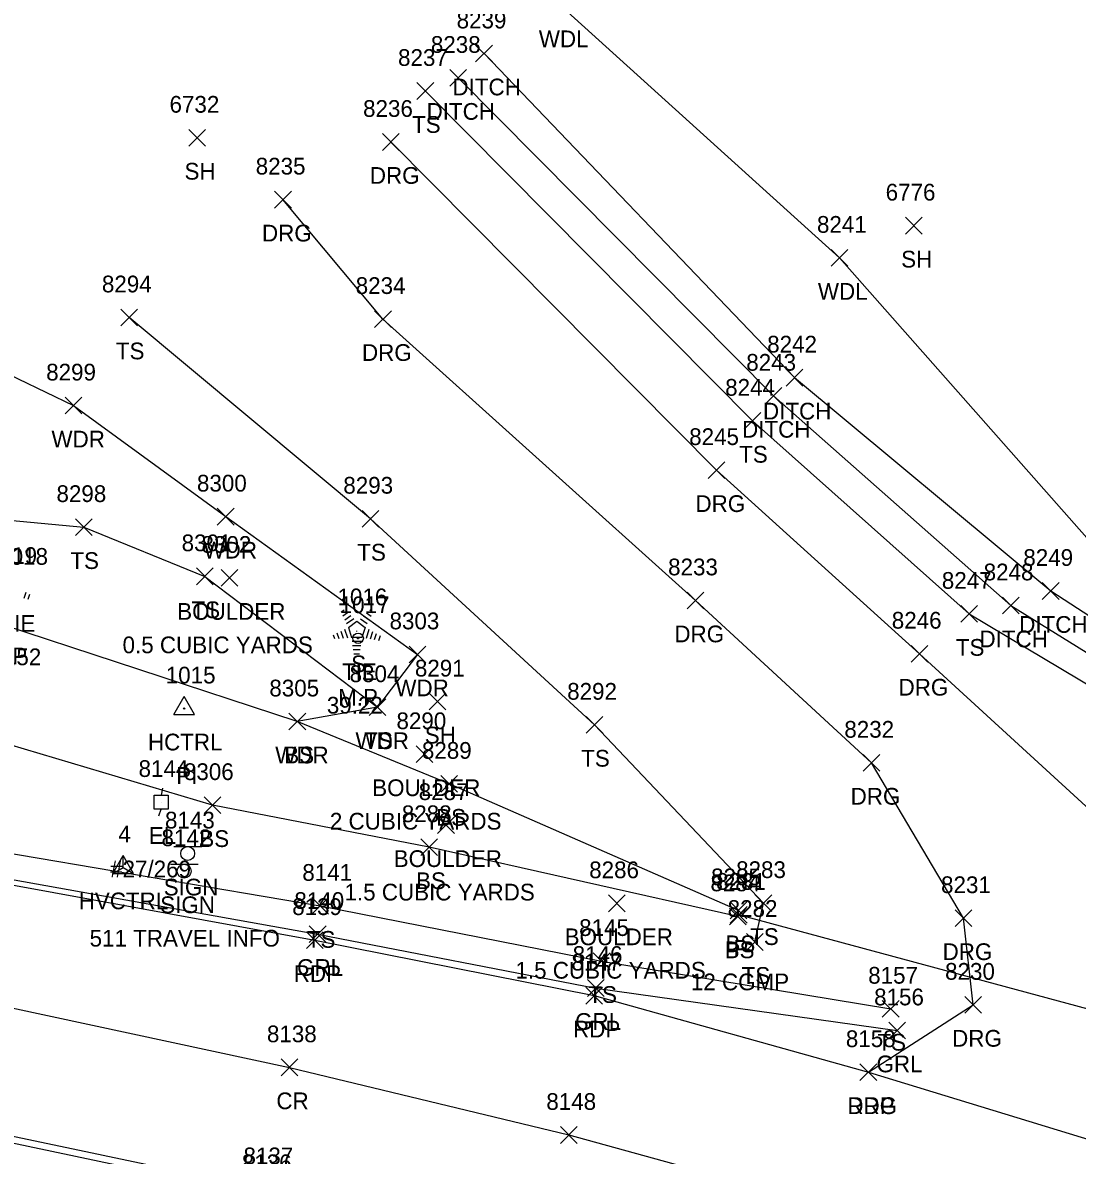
# Model space of a CAD drawing. Extents: x 1588028 to 1589597, y 137576 to 138176.
# Drawn here: x 1588986.3 to 1589112.3, y 137833.8 to 137969.2 of the extents above; entities that cross this region are included whole.
import ezdxf

# ---------------------------------------------------------------- set-up
doc = ezdxf.new("R2010")
doc.units = 0
for name, color, linetype in [('C_A', 7, 'Continuous'), ('C_C', 7, 'Continuous'), ('C_I', 7, 'Continuous'), ('CBP', 7, 'Continuous'), ('CPH', 7, 'Continuous'), ('CPSM', 7, 'Continuous'), ('D_A', 7, 'Continuous'), ('D_C', 7, 'Continuous'), ('D_I', 7, 'Continuous'), ('D_TIC', 7, 'Continuous'), ('DCP', 7, 'Continuous'), ('DD', 7, 'Continuous'), ('L_A', 7, 'Continuous'), ('L_C', 7, 'Continuous'), ('L_I', 7, 'Continuous'), ('L_TIC', 7, 'Continuous'), ('LAWA', 7, 'Continuous'), ('LELB', 7, 'Continuous'), ('LTC', 7, 'Continuous'), ('P_A', 7, 'Continuous'), ('P_I', 7, 'Continuous'), ('P_TIC', 7, 'Continuous'), ('PET', 7, 'Continuous'), ('PRC', 7, 'Continuous'), ('R_A', 7, 'Continuous'), ('R_I', 7, 'Continuous'), ('R_TIC', 7, 'Continuous'), ('RDG', 7, 'Continuous'), ('RGR', 7, 'Continuous'), ('S_A', 7, 'Continuous'), ('S_C', 7, 'Continuous'), ('S_I', 7, 'Continuous'), ('SSGN', 7, 'Continuous'), ('U_A', 7, 'Continuous'), ('U_C', 7, 'Continuous'), ('U_I', 7, 'Continuous'), ('UEPT', 7, 'Continuous')]:
    doc.layers.add(name, color=color, linetype=linetype)

msp = doc.modelspace()

# ---------------------------------------------------------------- linework, layer by layer
at = {"layer": 'CBP'}
for radius in [0.625, 0.0833]:
    msp.add_circle((1589026.39, 137895.62), radius, dxfattribs=at)
at = {"layer": 'CPH'}
for p, q in [((1589004.35, 137886.5), (1589005.6, 137888.66)), ((1589006.85, 137886.5), (1589005.6, 137888.66)), ((1589004.35, 137886.5), (1589006.85, 137886.5)), ((1589005.6, 137887.22), (1589005.6, 137887.22))]:
    msp.add_line(p, q, dxfattribs=at)
msp.add_circle((1589005.6, 137887.22), 0.0833, dxfattribs=at)
at = {"layer": 'CPSM'}
for p, q in [((1588997.06, 137867.52), (1588998.31, 137869.68)), ((1588999.56, 137867.52), (1588998.31, 137869.68)), ((1588998.31, 137868.24), (1588998.31, 137869.68)), ((1588997.06, 137867.52), (1588998.31, 137868.24)), ((1588997.06, 137867.52), (1588999.56, 137867.52)), ((1588998.31, 137868.24), (1588998.31, 137868.24)), ((1588998.31, 137868.24), (1588999.56, 137867.52))]:
    msp.add_line(p, q, dxfattribs=at)
at = {"layer": 'D_TIC'}
for points in [[(1589040.43, 137964.49), (1589042.43, 137966.49)], [(1589042.43, 137964.49), (1589040.43, 137966.49)], [(1589037.34, 137961.57), (1589039.34, 137963.57)], [(1589039.34, 137961.57), (1589037.34, 137963.57)], [(1589077.53, 137925.76), (1589079.53, 137927.76)], [(1589079.53, 137925.76), (1589077.53, 137927.76)], [(1589075.03, 137923.59), (1589077.03, 137925.59)], [(1589077.03, 137923.59), (1589075.03, 137925.59)], [(1589108.15, 137900.27), (1589110.15, 137902.27)], [(1589110.15, 137900.27), (1589108.15, 137902.27)], [(1589103.4, 137898.54), (1589105.4, 137900.54)], [(1589105.4, 137898.54), (1589103.4, 137900.54)], [(1589070.86, 137861.56), (1589072.86, 137863.56)], [(1589072.86, 137861.56), (1589070.86, 137863.56)]]:
    msp.add_lwpolyline(points, dxfattribs=at)
at = {"layer": 'DCP'}
msp.add_lwpolyline([(1589168.99, 137836.35), (1589071.86, 137862.56)], dxfattribs=at)
at = {"layer": 'DD'}
for points in [[(1589041.43, 137965.49), (1589078.53, 137926.76), (1589109.15, 137901.27), (1589128.72, 137888.57), (1589151.77, 137873.1)], [(1589038.34, 137962.57), (1589076.03, 137924.59), (1589104.4, 137899.54), (1589125.75, 137886.32), (1589152.64, 137869.01)]]:
    msp.add_lwpolyline(points, dxfattribs=at)
at = {"layer": 'L_TIC'}
for points in [[(1589033.42, 137960.01), (1589035.42, 137962.01)], [(1589035.42, 137960.01), (1589033.42, 137962.01)], [(1589006.15, 137954.42), (1589008.15, 137956.42)], [(1589008.15, 137954.42), (1589006.15, 137956.42)], [(1589091.8, 137943.92), (1589093.8, 137945.92)], [(1589093.8, 137943.92), (1589091.8, 137945.92)], [(1589082.91, 137940.07), (1589084.91, 137942.07)], [(1589084.91, 137940.07), (1589082.91, 137942.07)], [(1588998.03, 137932.95), (1589000.03, 137934.95)], [(1589000.03, 137932.95), (1588998.03, 137934.95)], [(1588991.38, 137922.42), (1588993.38, 137924.42)], [(1588993.38, 137922.42), (1588991.38, 137924.42)], [(1589072.51, 137920.6), (1589074.51, 137922.6)], [(1589074.51, 137920.6), (1589072.51, 137922.6)], [(1589009.56, 137909.15), (1589011.56, 137911.15)], [(1589011.56, 137909.15), (1589009.56, 137911.15)], [(1589026.88, 137908.9), (1589028.88, 137910.9)], [(1589028.88, 137908.9), (1589026.88, 137910.9)], [(1588992.6, 137907.9), (1588994.6, 137909.9)], [(1588994.6, 137907.9), (1588992.6, 137909.9)], [(1589007.07, 137902.02), (1589009.07, 137904.02)], [(1589009.07, 137902.02), (1589007.07, 137904.02)], [(1589010.01, 137901.83), (1589012.01, 137903.83)], [(1589012.01, 137901.83), (1589010.01, 137903.83)], [(1589098.4, 137897.53), (1589100.4, 137899.53)], [(1589100.4, 137897.53), (1589098.4, 137899.53)], [(1589032.48, 137892.69), (1589034.48, 137894.69)], [(1589034.48, 137892.69), (1589032.48, 137894.69)], [(1589027.71, 137886.38), (1589029.71, 137888.38)], [(1589029.71, 137886.38), (1589027.71, 137888.38)], [(1589027.71, 137886.38), (1589029.71, 137888.38)], [(1589029.71, 137886.38), (1589027.71, 137888.38)], [(1589034.86, 137887.05), (1589036.86, 137889.05)], [(1589036.86, 137887.05), (1589034.86, 137889.05)], [(1589018.12, 137884.67), (1589020.12, 137886.67)], [(1589020.12, 137884.67), (1589018.12, 137886.67)], [(1589018.12, 137884.67), (1589020.12, 137886.67)], [(1589020.12, 137884.67), (1589018.12, 137886.67)], [(1589053.63, 137884.28), (1589055.63, 137886.28)], [(1589055.63, 137884.28), (1589053.63, 137886.28)], [(1589033.32, 137880.76), (1589035.32, 137882.76)], [(1589035.32, 137880.76), (1589033.32, 137882.76)], [(1589036.28, 137877.22), (1589038.28, 137879.22)], [(1589038.28, 137877.22), (1589036.28, 137879.22)], [(1589007.97, 137874.68), (1589009.97, 137876.68)], [(1589009.97, 137874.68), (1589007.97, 137876.68)], [(1589035.89, 137872.29), (1589037.89, 137874.29)], [(1589037.89, 137872.29), (1589035.89, 137874.29)], [(1589033.87, 137869.65), (1589035.87, 137871.65)], [(1589035.87, 137869.65), (1589033.87, 137871.65)], [(1589056.31, 137862.95), (1589058.31, 137864.95)], [(1589058.31, 137862.95), (1589056.31, 137864.95)], [(1589073.82, 137862.97), (1589075.82, 137864.97)], [(1589075.82, 137862.97), (1589073.82, 137864.97)], [(1589020.85, 137862.64), (1589022.85, 137864.64)], [(1589022.85, 137862.64), (1589020.85, 137864.64)], [(1589070.83, 137862.11), (1589072.83, 137864.11)], [(1589072.83, 137862.11), (1589070.83, 137864.11)], [(1589070.75, 137861.39), (1589072.75, 137863.39)], [(1589072.75, 137861.39), (1589070.75, 137863.39)], [(1589070.75, 137861.39), (1589072.75, 137863.39)], [(1589072.75, 137861.39), (1589070.75, 137863.39)], [(1589072.81, 137858.33), (1589074.81, 137860.33)], [(1589074.81, 137858.33), (1589072.81, 137860.33)], [(1589054.49, 137856.05), (1589056.49, 137858.05)], [(1589056.49, 137856.05), (1589054.49, 137858.05)], [(1589089.03, 137850.35), (1589091.03, 137852.35)], [(1589091.03, 137850.35), (1589089.03, 137852.35)]]:
    msp.add_lwpolyline(points, dxfattribs=at)
at = {"layer": 'LAWA'}
for points in [[(1589050.56, 137971.24), (1589083.91, 137941.07), (1589116.19, 137904.57), (1589140.2, 137894.13), (1589149.91, 137879.08)], [(1588979.13, 137929.8), (1588992.38, 137923.42), (1589010.56, 137910.15), (1589033.48, 137893.69), (1589028.71, 137887.38), (1589019.12, 137885.67), (1588981.21, 137898.09), (1588946.07, 137903.66)]]:
    msp.add_lwpolyline(points, dxfattribs=at)
at = {"layer": 'LELB'}
for points in [[(1589034.42, 137961.01), (1589073.51, 137921.6), (1589099.4, 137898.53), (1589123.8, 137884), (1589148.54, 137869.03), (1589154.8, 137847.86), (1589161.44, 137841.64), (1589169.34, 137837.46)], [(1589073.81, 137859.33), (1589074.82, 137863.97), (1589054.63, 137885.28), (1589027.88, 137909.9), (1588999.03, 137933.95)], [(1588967.42, 137926.48), (1588976.15, 137910.53), (1588993.6, 137908.9), (1589008.07, 137903.02), (1589028.71, 137887.38)], [(1589071.75, 137862.39), (1589071.83, 137863.11), (1589037.28, 137878.22), (1589019.12, 137885.67)], [(1589071.75, 137862.39), (1589034.87, 137870.65), (1589008.97, 137875.68), (1588978.98, 137884.6), (1588952.74, 137884.36)], [(1588954.6, 137874.92), (1588981.41, 137870.49), (1589021.85, 137863.64), (1589055.49, 137857.05), (1589090.03, 137851.35)]]:
    msp.add_lwpolyline(points, dxfattribs=at)
at = {"layer": 'LTC'}
for p, q in [((1588986.67, 137901.1), (1588986.43, 137900.37)), ((1588987.11, 137900.85), (1588986.93, 137900.27)), ((1589024.37, 137898.76), (1589024.73, 137899.02)), ((1589024.58, 137898.3), (1589025.11, 137898.68)), ((1589027.4, 137898.66), (1589027.95, 137898.26)), ((1589027.77, 137899), (1589028.19, 137898.7)), ((1589024.79, 137897.83), (1589025.5, 137898.34)), ((1589025, 137897.37), (1589025.88, 137898)), ((1589025.23, 137896.91), (1589026.24, 137897.65)), ((1589026.24, 137897.65), (1589027.24, 137896.92)), ((1589026.66, 137897.96), (1589027.47, 137897.37)), ((1589027.03, 137898.31), (1589027.71, 137897.81)), ((1589023.41, 137896.04), (1589023.56, 137895.58)), ((1589023.86, 137896.26), (1589024.07, 137895.61)), ((1589024.32, 137896.48), (1589024.59, 137895.64)), ((1589024.77, 137896.69), (1589025.1, 137895.67)), ((1589025.23, 137896.91), (1589025.61, 137895.72)), ((1589027.24, 137896.92), (1589026.84, 137895.72)), ((1589027.67, 137896.65), (1589027.33, 137895.61)), ((1589028.12, 137896.4), (1589027.83, 137895.52)), ((1589028.56, 137896.15), (1589028.32, 137895.42)), ((1589026.84, 137895.72), (1589025.61, 137895.72)), ((1589026.81, 137895.22), (1589025.66, 137895.22)), ((1589026.72, 137894.72), (1589025.73, 137894.72)), ((1589029.01, 137895.9), (1589028.82, 137895.33)), ((1589026.64, 137894.22), (1589025.81, 137894.22)), ((1589026.55, 137893.72), (1589025.88, 137893.72))]:
    msp.add_line(p, q, dxfattribs=at)
at = {"layer": 'P_TIC'}
for points in [[(1589020.21, 137858.55), (1589022.21, 137860.55)], [(1589022.21, 137858.55), (1589020.21, 137860.55)], [(1589053.58, 137851.92), (1589055.58, 137853.92)], [(1589055.58, 137851.92), (1589053.58, 137853.92)], [(1589017.19, 137843.35), (1589019.19, 137845.35)], [(1589019.19, 137843.35), (1589017.19, 137845.35)], [(1589086.36, 137842.77), (1589088.36, 137844.77)], [(1589088.36, 137842.77), (1589086.36, 137844.77)], [(1589050.57, 137835.27), (1589052.57, 137837.27)], [(1589052.57, 137835.27), (1589050.57, 137837.27)]]:
    msp.add_lwpolyline(points, dxfattribs=at)
at = {"layer": 'PET'}
for points in [[(1588976.42, 137837.98), (1588964.71, 137855.4), (1588953.74, 137871.46), (1588980.82, 137866.91), (1589021.21, 137859.55), (1589054.58, 137852.92), (1589087.36, 137843.77), (1589127.64, 137831.45), (1589150.05, 137824.37), (1589196.14, 137808.72), (1589243.87, 137790.96), (1589276.87, 137778.08), (1589322.25, 137759.62), (1589367.82, 137740.82), (1589401.87, 137726.11), (1589432.81, 137712.85), (1589459.76, 137701.46)], [(1588976.42, 137837.98), (1589015.38, 137829.77), (1589047.77, 137821.87), (1589087.62, 137811.07), (1589117.34, 137801.67), (1589165.82, 137785.25), (1589185.23, 137778.17), (1589232.28, 137760.8), (1589265.32, 137747.81), (1589310.31, 137729.83), (1589359.63, 137709.23), (1589389.55, 137696.8), (1589422.31, 137682.69), (1589446.91, 137672.54)]]:
    msp.add_lwpolyline(points, dxfattribs=at)
at = {"layer": 'PRC'}
msp.add_lwpolyline([(1588964.71, 137855.4), (1588980.14, 137852.51), (1589018.19, 137844.35), (1589051.57, 137836.27), (1589092.27, 137825.07), (1589122.68, 137816.23), (1589170.7, 137800.29), (1589190.72, 137793.38), (1589238.44, 137775.62), (1589271.31, 137762.4), (1589315.94, 137744.35), (1589366.22, 137723.58), (1589395.71, 137710.87), (1589428.18, 137697.42), (1589453.33, 137686.42)], dxfattribs=at)
at = {"layer": 'R_TIC'}
for points in [[(1589029.3, 137953.92), (1589031.3, 137955.92)], [(1589031.3, 137953.92), (1589029.3, 137955.92)], [(1589016.41, 137947.03), (1589018.41, 137949.03)], [(1589018.41, 137947.03), (1589016.41, 137949.03)], [(1589028.36, 137932.76), (1589030.36, 137934.76)], [(1589030.36, 137932.76), (1589028.36, 137934.76)], [(1589068.21, 137914.71), (1589070.21, 137916.71)], [(1589070.21, 137914.71), (1589068.21, 137916.71)], [(1589065.69, 137899.14), (1589067.69, 137901.14)], [(1589067.69, 137899.14), (1589065.69, 137901.14)], [(1589092.48, 137892.77), (1589094.48, 137894.77)], [(1589094.48, 137892.77), (1589092.48, 137894.77)], [(1589086.75, 137879.74), (1589088.75, 137881.74)], [(1589088.75, 137879.74), (1589086.75, 137881.74)], [(1589097.74, 137861.17), (1589099.74, 137863.17)], [(1589099.74, 137861.17), (1589097.74, 137863.17)], [(1589020.55, 137859.28), (1589022.55, 137861.28)], [(1589022.55, 137859.28), (1589020.55, 137861.28)], [(1589053.78, 137852.83), (1589055.78, 137854.83)], [(1589055.78, 137852.83), (1589053.78, 137854.83)], [(1589098.88, 137850.82), (1589100.88, 137852.82)], [(1589100.88, 137850.82), (1589098.88, 137852.82)], [(1589089.79, 137847.76), (1589091.79, 137849.76)], [(1589091.79, 137847.76), (1589089.79, 137849.76)], [(1589086.36, 137842.77), (1589088.36, 137844.77)], [(1589088.36, 137842.77), (1589086.36, 137844.77)]]:
    msp.add_lwpolyline(points, dxfattribs=at)
at = {"layer": 'RDG'}
for points in [[(1589030.3, 137954.92), (1589069.21, 137915.71), (1589093.48, 137893.77), (1589119.98, 137869.52), (1589132.81, 137847.36), (1589143.24, 137832.79), (1589147.71, 137827.91)], [(1589087.36, 137843.77), (1589099.88, 137851.82), (1589098.74, 137862.17), (1589087.75, 137880.74), (1589066.69, 137900.14), (1589029.36, 137933.76), (1589017.41, 137948.03)]]:
    msp.add_lwpolyline(points, dxfattribs=at)
at = {"layer": 'RGR'}
for points in [[(1588954.82, 137872.1), (1588981.04, 137867.52), (1589021.55, 137860.28), (1589054.78, 137853.83), (1589090.79, 137848.76)], [(1588981.28, 137836.13), (1589015.23, 137828.95), (1589047.72, 137821.35), (1589087.45, 137810.42), (1589116.48, 137799.61), (1589136.35, 137790.83)]]:
    msp.add_lwpolyline(points, dxfattribs=at)
at = {"layer": 'SSGN'}
for p, q in [((1589004.37, 137870.74), (1589007.71, 137870.74)), ((1589006.02, 137869.91), (1589006.02, 137869.91)), ((1589003.95, 137868.63), (1589007.29, 137868.63)), ((1589005.6, 137867.8), (1589005.6, 137867.8))]:
    msp.add_line(p, q, dxfattribs=at)
for centre in [(1589006.02, 137869.91), (1589005.6, 137867.8)]:
    msp.add_circle(centre, 0.833, dxfattribs=at)
at = {"layer": 'UEPT'}
for p, q in [((1589003.01, 137877.72), (1589002.84, 137876.89)), ((1589002.01, 137875.22), (1589002.01, 137876.89)), ((1589002.01, 137876.89), (1589003.67, 137876.89)), ((1589002.84, 137876.05), (1589002.84, 137876.05)), ((1589003.67, 137876.89), (1589003.67, 137875.22)), ((1589003.67, 137875.22), (1589002.01, 137875.22)), ((1589002.59, 137874.39), (1589002.84, 137875.22))]:
    msp.add_line(p, q, dxfattribs=at)

# ---------------------------------------------------------------- texts
at = {"layer": 'C_A'}
for s, p in [('TIE', (1588983.66, 137896.4)), ('TIE', (1589024.47, 137890.62)), ('HCTRL', (1589001.27, 137882.22)), ('HVCTRL', (1588993, 137863.24))]:
    msp.add_text(s, height=2, dxfattribs=at).set_placement(p)
at = {"layer": 'C_C'}
for s, p in [('35.52', (1588981.83, 137892.4)), ('39.22', (1589022.65, 137886.62)), ('PI', (1589004.66, 137878.22))]:
    msp.add_text(s, height=2, dxfattribs=at).set_placement(p)
at = {"layer": 'C_I'}
for s, p in [('1018', (1588983.38, 137904.4)), ('1017', (1589024.19, 137898.62)), ('1015', (1589003.4, 137890.22)), ('4', (1588997.74, 137871.24))]:
    msp.add_text(s, height=2, dxfattribs=at).set_placement(p)
at = {"layer": 'D_A'}
for s, p in [('DITCH', (1589037.66, 137960.49)), ('DITCH', (1589034.57, 137957.57)), ('DITCH', (1589074.77, 137921.76)), ('DITCH', (1589072.27, 137919.59)), ('DITCH', (1589105.39, 137896.27)), ('DITCH', (1589100.64, 137894.54)), ('P', (1589071.24, 137857.56))]:
    msp.add_text(s, height=2, dxfattribs=at).set_placement(p)
at = {"layer": 'D_C'}
msp.add_text('12 CGMP', height=2, dxfattribs=at).set_placement((1589066.15, 137853.56))
at = {"layer": 'D_I'}
for s, p in [('8239', (1589038.16, 137968.49)), ('8238', (1589035.08, 137965.57)), ('8242', (1589075.27, 137929.76)), ('8243', (1589072.77, 137927.59)), ('8249', (1589105.88, 137904.27)), ('8248', (1589101.14, 137902.54)), ('8281', (1589069.17, 137865.56))]:
    msp.add_text(s, height=2, dxfattribs=at).set_placement(p)
at = {"layer": 'L_A'}
for s, p in [('WDL', (1589047.98, 137966.24)), ('TS', (1589032.83, 137956.01)), ('SH', (1589005.64, 137950.42)), ('SH', (1589091.28, 137939.92)), ('WDL', (1589081.33, 137936.07)), ('TS', (1588997.44, 137928.95)), ('WDR', (1588989.74, 137918.42)), ('TS', (1589071.92, 137916.6)), ('WDR', (1589007.92, 137905.15)), ('TS', (1589026.29, 137904.9)), ('TS', (1588992, 137903.9)), ('TS', (1589006.48, 137898.02)), ('BOULDER', (1589004.77, 137897.83)), ('TS', (1589097.81, 137893.53)), ('S', (1589025.56, 137891.56)), ('WDR', (1589030.84, 137888.69)), ('WDR', (1589026.07, 137882.38)), ('TS', (1589027.12, 137882.38)), ('SH', (1589034.35, 137883.05)), ('WDR', (1589016.48, 137880.67)), ('BS', (1589017.56, 137880.67)), ('TS', (1589053.04, 137880.28)), ('BOULDER', (1589028.07, 137876.76)), ('BS', (1589035.72, 137873.22)), ('BS', (1589007.41, 137870.68)), ('BOULDER', (1589030.64, 137868.29)), ('BS', (1589033.31, 137865.65)), ('BOULDER', (1589051.07, 137858.95)), ('TS', (1589073.23, 137858.97)), ('TS', (1589020.26, 137858.64)), ('BS', (1589070.19, 137857.39)), ('BS', (1589070.19, 137857.39)), ('BS', (1589070.28, 137858.11)), ('TS', (1589072.22, 137854.33)), ('TS', (1589053.9, 137852.05)), ('TS', (1589088.44, 137846.35))]:
    msp.add_text(s, height=2, dxfattribs=at).set_placement(p)
at = {"layer": 'L_C'}
for s, p in [('0.5 CUBIC YARDS', (1588998.24, 137893.83)), ('M.P', (1588982.1, 137892.5)), ('M.P', (1589024, 137887.56)), ('2 CUBIC YARDS', (1589023.01, 137872.76)), ('1.5 CUBIC YARDS', (1589024.76, 137864.29)), ('1.5 CUBIC YARDS', (1589045.19, 137854.95))]:
    msp.add_text(s, height=2, dxfattribs=at).set_placement(p)
at = {"layer": 'L_I'}
for s, p in [('8237', (1589031.16, 137964.01)), ('6732', (1589003.85, 137958.42)), ('6776', (1589089.43, 137947.92)), ('8241', (1589081.22, 137944.07)), ('8294', (1588995.77, 137936.95)), ('8299', (1588989.11, 137926.42)), ('8244', (1589070.25, 137924.6)), ('8300', (1589007.13, 137913.15)), ('8293', (1589024.62, 137912.9)), ('8298', (1588990.34, 137911.9)), ('8301', (1589005.3, 137906.02)), ('8302', (1589007.67, 137905.83)), ('1019', (1588982.07, 137904.5)), ('8247', (1589096.14, 137901.53)), ('1016', (1589023.92, 137899.56)), ('8303', (1589030.14, 137896.69)), ('8304', (1589025.37, 137890.38)), ('8304', (1589025.37, 137890.38)), ('8291', (1589033.17, 137891.05)), ('8305', (1589015.78, 137888.67)), ('8305', (1589015.78, 137888.67)), ('8292', (1589051.37, 137888.28)), ('8290', (1589030.97, 137884.76)), ('8289', (1589034.01, 137881.22)), ('8306', (1589005.57, 137878.68)), ('8287', (1589033.63, 137876.29)), ('8288', (1589031.61, 137873.65)), ('8286', (1589054, 137866.95)), ('8283', (1589071.56, 137866.97)), ('8141', (1589019.72, 137866.64)), ('8285', (1589068.57, 137866.11)), ('8284', (1589068.49, 137865.39)), ('8284', (1589068.49, 137865.39)), ('8282', (1589070.55, 137862.33)), ('8145', (1589052.8, 137860.05)), ('8157', (1589087.34, 137854.35))]:
    msp.add_text(s, height=2, dxfattribs=at).set_placement(p)
at = {"layer": 'LTC'}
msp.add_text('.', height=1.04, rotation=270, dxfattribs=at).set_placement((1589026.12, 137896.66))
at = {"layer": 'P_A'}
for s, p in [('RDP', (1589018.7, 137854.55)), ('RDP', (1589052.07, 137847.92)), ('CR', (1589016.62, 137839.35)), ('RDP', (1589084.85, 137838.77))]:
    msp.add_text(s, height=2, dxfattribs=at).set_placement(p)
at = {"layer": 'P_I'}
for s, p in [('8139', (1589018.51, 137862.55)), ('8147', (1589051.88, 137855.92)), ('8138', (1589015.49, 137847.35)), ('8158', (1589084.67, 137846.77)), ('8148', (1589048.88, 137839.27)), ('8137', (1589012.69, 137832.77))]:
    msp.add_text(s, height=2, dxfattribs=at).set_placement(p)
at = {"layer": 'R_A'}
for s, p in [('DRG', (1589027.79, 137949.92)), ('DRG', (1589014.9, 137943.03)), ('DRG', (1589026.85, 137928.76)), ('DRG', (1589066.7, 137910.71)), ('DRG', (1589064.18, 137895.14)), ('DRG', (1589090.97, 137888.77)), ('DRG', (1589085.24, 137875.74)), ('DRG', (1589096.23, 137857.17)), ('GRL', (1589019.09, 137855.28)), ('GRL', (1589052.32, 137848.83)), ('DRG', (1589097.37, 137846.82)), ('GRL', (1589088.34, 137843.76)), ('DRG', (1589084.85, 137838.77))]:
    msp.add_text(s, height=2, dxfattribs=at).set_placement(p)
at = {"layer": 'R_I'}
for s, p in [('8236', (1589026.98, 137957.92)), ('8235', (1589014.15, 137951.03)), ('8234', (1589026.1, 137936.76)), ('8245', (1589065.95, 137918.71)), ('8233', (1589063.43, 137903.14)), ('8246', (1589090.16, 137896.77)), ('8232', (1589084.49, 137883.74)), ('8231', (1589096.05, 137865.17)), ('8140', (1589018.77, 137863.28)), ('8146', (1589052.03, 137856.83)), ('8230', (1589096.53, 137854.82)), ('8156', (1589088.05, 137851.76)), ('8158', (1589084.67, 137846.77)), ('8136', (1589012.49, 137831.95))]:
    msp.add_text(s, height=2, dxfattribs=at).set_placement(p)
at = {"layer": 'S_A'}
for p in [(1589003.16, 137864.89), (1589002.74, 137862.78)]:
    msp.add_text('SIGN', height=2, dxfattribs=at).set_placement(p)
at = {"layer": 'S_C'}
msp.add_text('511 TRAVEL INFO', height=2, dxfattribs=at).set_placement((1588994.3, 137858.78))
at = {"layer": 'S_I'}
for s, p in [('8143', (1589003.31, 137872.89)), ('8142', (1589002.89, 137870.78))]:
    msp.add_text(s, height=2, dxfattribs=at).set_placement(p)
at = {"layer": 'U_A'}
msp.add_text('EL', height=2, dxfattribs=at).set_placement((1589001.38, 137871.05))
at = {"layer": 'U_C'}
msp.add_text('#27/269', height=2, dxfattribs=at).set_placement((1588996.75, 137867.05))
at = {"layer": 'U_I'}
msp.add_text('8144', height=2, dxfattribs=at).set_placement((1589000.15, 137879.05))

doc.saveas('drawing.dxf')
